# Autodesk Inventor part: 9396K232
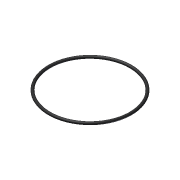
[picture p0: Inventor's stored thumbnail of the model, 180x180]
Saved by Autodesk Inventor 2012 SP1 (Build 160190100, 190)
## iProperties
Created: 2012-03
Part Number: 9396K232
Material: Silicone
Document SubType Name: Modeling
Designer: jdh
Density: 1.25 g/cm^3
Mass: 4.02619 g
Surface Area: 36.4918 cm^2
Volume: 3.22095 cm^3
Author: jdh
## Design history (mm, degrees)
sketch "Sketch1"
  geometry: L1 (-54.127, 1.765)-(-50.597, 1.765); L2 (-50.597, 1.765)-(-50.597, -1.765); L3 (-50.597, -1.765)-(-54.127, -1.765); L4 (-54.127, -1.765)-(-54.127, 1.765); L5 (-52.362, 0)-(0, 0); L6 (0, -2.471)-(0, 2.471) reference; C1 r 1.765 at (-52.362, 0)
  constraints: 10 end point, 4 tangent, 2 horizontal, 2 parallel, 1 centre point, 1 coincident, 1 perpendicular
  dimensions: "d0" = 54.1274 distance from line of L5.end L4 (= 0.5 x OD); "d1" = 50.5968 distance from line of L5.end L2 (= 0.5 x ID)
revolve "Revolution1" sketch "Sketch1" stored, may be unused: angle "d2" = 90 deg
body "Solid1"
other parameters: "ID" = 101.1936 [user parameter; used in 1 equation term], "OD" = 108.2548 [user parameter; used in 1 equation term]
